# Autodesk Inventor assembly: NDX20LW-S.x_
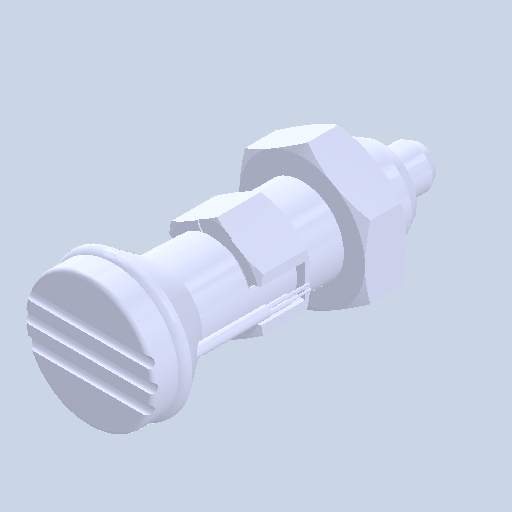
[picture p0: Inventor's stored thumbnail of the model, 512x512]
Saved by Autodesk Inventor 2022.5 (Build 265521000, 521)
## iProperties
Created: 2024-05
Part Number: NDX20LW-S.x_
Document SubType Name: Assembly
Designer: ImaoCorp
Author: ImaoCorp
Sending System: SOLIDWORKS 2022-2022290
MC: AMD64
MC_MODEL: Intel64 Family 6 Model 60 Stepping 3, GenuineIntel
OS: Windows_NT
FRU: Parasolid Version 33.1, build 260,  4-25-2022
FORMAT: text
GUISE: transmit
KEY: FILENDX20LW-S.x_t
DATE: Tue May 21 08:47:36 2024
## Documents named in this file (3)
- X:\14_SW2022-Inv2022\保留中\kipp\KME_データ\n\ndx20lw-s\NDX20LW-S.x_.iam
- X:\14_SW2022-Inv2022\保留中\kipp\KME_データ\n\ndx20lw-s\NDX20LW-S_01.ipt
- X:\14_SW2022-Inv2022\保留中\kipp\KME_データ\n\ndx20lw-s\NDX20LW-S_02.ipt
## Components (2 placed, 2 different names)
1. NDX20LW-S_01
2. NDX20LW-S_02
